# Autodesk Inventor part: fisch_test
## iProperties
Shininess: 64.0
Length Units: 11269
Angle Units: 11279
Time Units: 11290
Mass Units: 11283
Length Display Precision: 3
Angle Display Precision: 2
Compacted: True
Part Number: fisch_test
Document SubType Name: Modeling
Created: 2004-02
Material: Standard
Designer: juergen
Manufacturer: Standard
Standards Organization: Custom
Density: 0.0
Volumn: 0.0
Area: 0.0
PropertySet Name: Model Information
Control State: 0
Master: False
Checked Out: False
Author: juergen
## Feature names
1. Erhebung1
